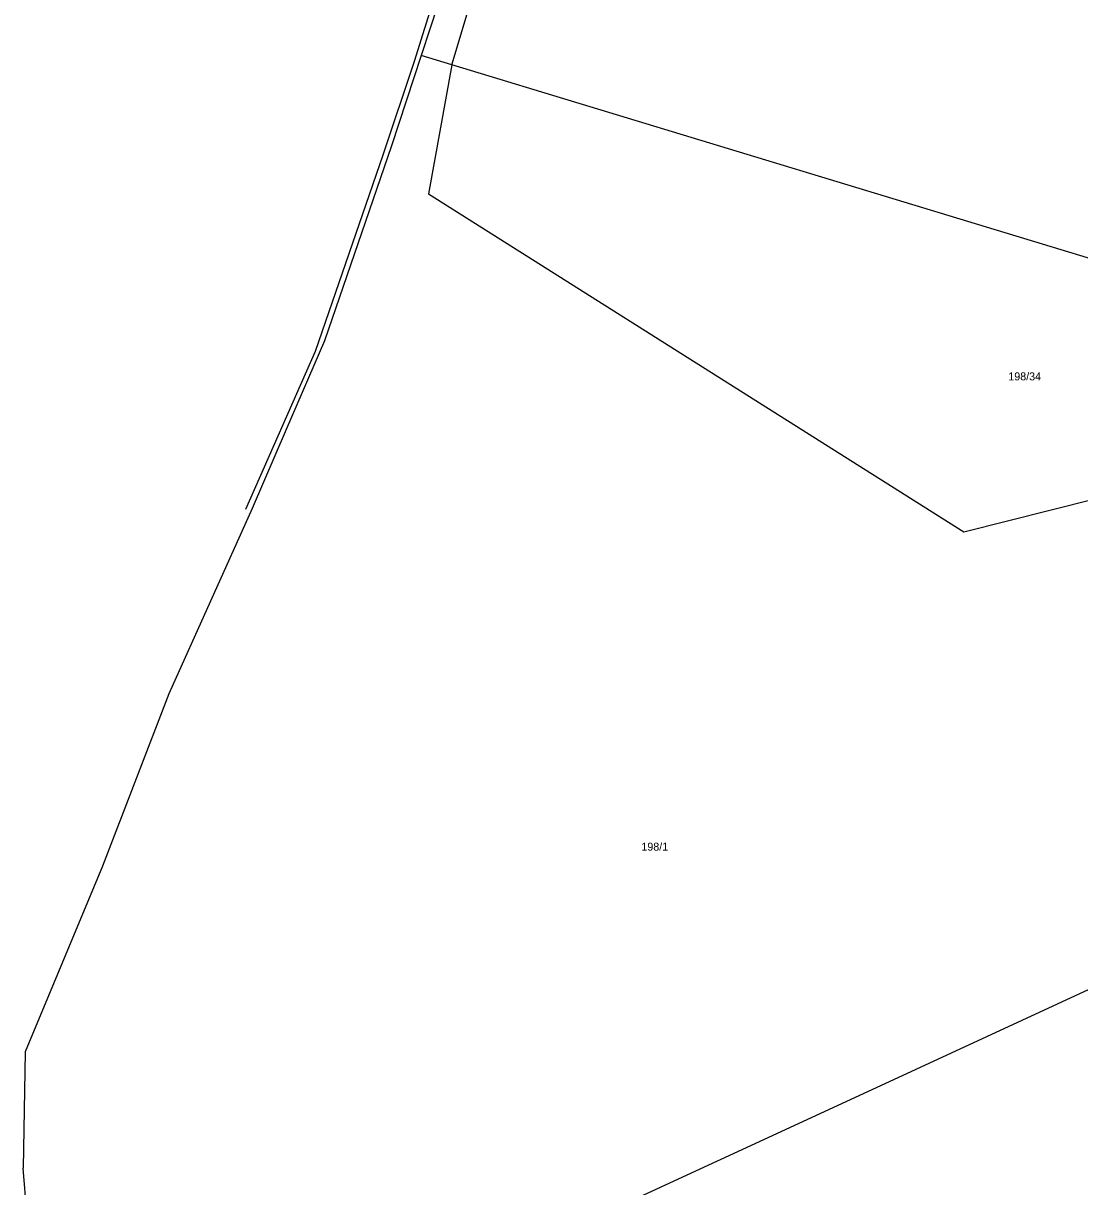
# Model space of a CAD drawing. Extents: x -882150 to -879379, y -1022570 to -1019819.
# Drawn here: x -880708.8 to -880484.4, y -1020448.8 to -1020201.6 of the extents above; entities that cross this region are included whole.
import ezdxf

# ---------------------------------------------------------------- set-up
doc = ezdxf.new("R2010")
doc.units = 0
for name, color, linetype in [('Hranice parcel', 7, 'Continuous'), ('Parcelní čísla', 7, 'Continuous'), ('Vnitřní kresba', 7, 'Continuous')]:
    doc.layers.add(name, color=color, linetype=linetype)

msp = doc.modelspace()

# ---------------------------------------------------------------- linework, layer by layer
at = {"layer": 'Hranice parcel'}
for p, q in [((-880622.4, -1020202.7), (-880624.3, -1020208.5)), ((-880624.3, -1020208.5), (-880630.6, -1020227.7)), ((-880617.77, -1020210.48), (-880624.3, -1020208.5)), ((-880630.6, -1020227.7), (-880644.8, -1020269.1)), ((-880644.8, -1020269.1), (-880652.96, -1020287.95)), ((-880652.96, -1020287.95), (-880660.2, -1020304.7)), ((-880707.2, -1020465.4), (-880708.82, -1020444.91))]:
    msp.add_line(p, q, dxfattribs=at)
for points in [[(-880600.6, -1020135.76), (-880605.8, -1020150.8), (-880617.7, -1020188.4), (-880622.4, -1020202.7)], [(-880617.77, -1020210.48), (-880603.54, -1020163.01), (-880600.6, -1020135.76)], [(-880617.77, -1020210.48), (-880622.75, -1020237.87), (-880508.97, -1020309.69), (-880453.04, -1020295.61), (-880342.22, -1020326.65), (-880338.05, -1020295.44)], [(-880338.05, -1020295.44), (-880470.83, -1020255.11), (-880617.77, -1020210.48)], [(-880660.2, -1020304.7), (-880677.9, -1020344.1), (-880692, -1020380.7), (-880708.4, -1020420.2), (-880708.82, -1020444.91)], [(-880682, -1020499), (-880673.83, -1020495.23), (-880595.38, -1020459.02), (-880526.65, -1020427.3), (-880443.12, -1020388.75), (-880366.39, -1020353.34), (-880317.99, -1020331), (-880274.92, -1020321.12), (-880262.73, -1020318.32)]]:
    msp.add_lwpolyline(points, dxfattribs=at)
at = {"layer": 'Vnitřní kresba'}
msp.add_lwpolyline([(-880589.65, -1019899.31), (-880587.82, -1019899.21), (-880491.2, -1019964.9), (-880494.11, -1019968.89), (-880541.64, -1020039.06), (-880542.42, -1020041.28), (-880545.34, -1020068.96), (-880546.12, -1020072.86), (-880579.04, -1020068.57), (-880579.82, -1020074.03), (-880597.35, -1020123.93), (-880607.48, -1020151.31), (-880625.79, -1020209.79), (-880632.41, -1020229.67), (-880646.83, -1020271.39), (-880661.64, -1020304.91)], dxfattribs=at)

# ---------------------------------------------------------------- texts
at = {"layer": 'Parcelní čísla'}
for s, p in [('198/34', (-880499.54, -1020277.51)), ('198/1', (-880577.5, -1020377.43))]:
    msp.add_text(s, height=1.7, dxfattribs=at).set_placement(p)

doc.saveas('drawing.dxf')
